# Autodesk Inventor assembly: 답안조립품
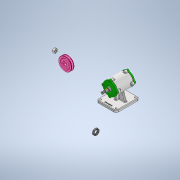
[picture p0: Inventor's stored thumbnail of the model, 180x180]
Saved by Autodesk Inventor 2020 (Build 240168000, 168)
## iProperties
Created: 2022-11
Part Number: 답안조립품
Document SubType Name: Assembly
Designer: owner
Author: owner
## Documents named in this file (12)
- C:\Users\owner\Desktop\721108V1016\답안조립품.iam
- C:\Users\owner\Desktop\721108V1016\본체.ipt
- C:\Users\owner\Desktop\721108V1016\V-벨트풀리.ipt
- C:\Users\owner\Desktop\721108V1016\개스킷.ipt
- C:\Users\owner\Desktop\721108V1016\너트 M12 x 1.25.ipt
- C:\Users\owner\Desktop\721108V1016\뒤커버.ipt
- C:\Users\owner\Desktop\721108V1016\베어링 6204.ipt
- C:\Users\owner\Desktop\721108V1016\볼트 M4 x 12.ipt
- C:\Users\owner\Desktop\721108V1016\앞커버.ipt
- C:\Users\owner\Desktop\721108V1016\오일 실.ipt
- C:\Users\owner\Desktop\721108V1016\축.ipt
- C:\Users\owner\Desktop\721108V1016\키 4 x 4.ipt
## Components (8 placed, 6 different names)
1. V-벨트풀리:1
2. 개스킷:1
3. KS B 1012 클래스 1 일반 - 미터 M12x1.25:1
4. KS B 2023 6204 - 20 x 47 x 14:1
5. KS B 2804 D D - 20 32 8:1
6. KS B 1311 (I) 4 x 4 x 12:1
7. KS B 2023 6204 - 20 x 47 x 14:2
8. 개스킷:2
